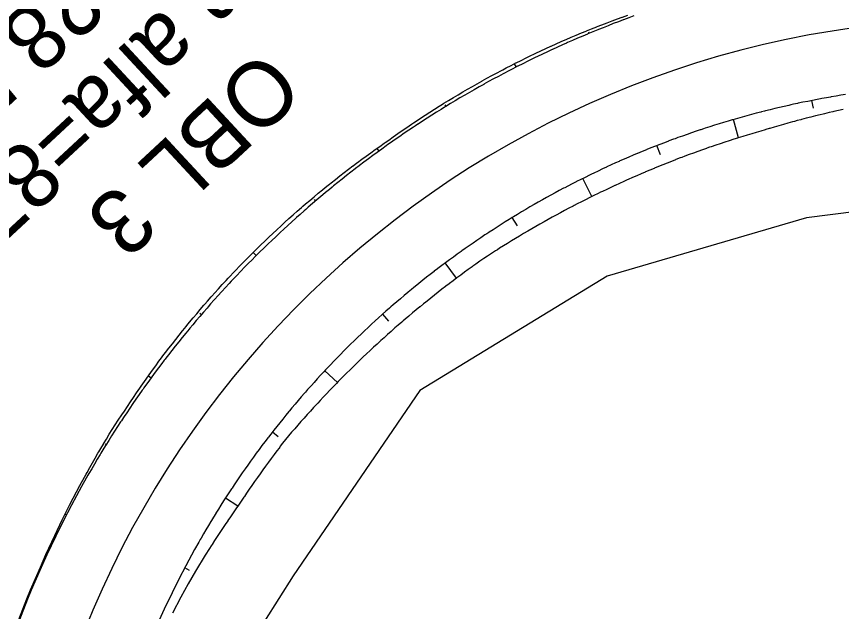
# Model space of a CAD drawing. Extents: x -583470 to -583050, y -1165714 to -1165417.
# Drawn here: x -583359.68 to -583334.17, y -1165593.45 to -1165575.06 of the extents above; entities that cross this region are included whole.
import ezdxf

# ---------------------------------------------------------------- set-up
doc = ezdxf.new("R2010")
doc.units = 0
for name, color, linetype in [('Hranice parcel', 7, 'Continuous'), ('Parcelní čísla', 7, 'Continuous'), ('Rám', 7, 'Continuous'), ('Sítě', 7, 'Continuous'), ('Šrafy', 7, 'Continuous')]:
    doc.layers.add(name, color=color, linetype=linetype)

msp = doc.modelspace()

# ---------------------------------------------------------------- linework, layer by layer
at = {"layer": 'Parcelní čísla'}
msp.add_arc((-583329.697, -1165605.137), 30, 89.2824, 176.4435, dxfattribs=at)
at = {"layer": 'Rám'}
msp.add_lwpolyline([(-583202.69, -1165538.68), (-583225.12, -1165531.51), (-583247.31, -1165545.19), (-583283.21, -1165574.06), (-583292.71, -1165580.22), (-583304.73, -1165581.14), (-583316.86, -1165578.96), (-583335.26, -1165581.29), (-583341.42, -1165583.09), (-583347.21, -1165586.62), (-583351.13, -1165592.35), (-583353.34, -1165595.85), (-583354.98, -1165601.64), (-583352.56, -1165623.43)], dxfattribs=at)
at = {"layer": 'Sítě'}
for points in [[(-583359.677, -1165593.89), (-583359.355, -1165593.062), (-583359.242, -1165592.784), (-583358.941, -1165592.078), (-583358.77, -1165591.694), (-583358.498, -1165591.106), (-583358.262, -1165590.619), (-583358.026, -1165590.148), (-583357.718, -1165589.561), (-583357.579, -1165589.304), (-583357.525, -1165589.205), (-583357.497, -1165589.155), (-583357.414, -1165589.006), (-583357.33, -1165588.857), (-583357.246, -1165588.709), (-583357.16, -1165588.562), (-583357.137, -1165588.523), (-583357.074, -1165588.415), (-583356.992, -1165588.278), (-583356.986, -1165588.268), (-583356.898, -1165588.122), (-583356.809, -1165587.977), (-583356.719, -1165587.832), (-583356.629, -1165587.687), (-583356.536, -1165587.544), (-583356.513, -1165587.51), (-583356.44, -1165587.403), (-583356.42, -1165587.374), (-583356.343, -1165587.262), (-583356.25, -1165587.119), (-583356.156, -1165586.977), (-583356.061, -1165586.835), (-583355.966, -1165586.694), (-583355.869, -1165586.553), (-583355.848, -1165586.522), (-583355.823, -1165586.486), (-583355.772, -1165586.413), (-583355.674, -1165586.273), (-583355.575, -1165586.134), (-583355.475, -1165585.996), (-583355.375, -1165585.858), (-583355.274, -1165585.72), (-583355.197, -1165585.618), (-583355.171, -1165585.584), (-583355.151, -1165585.556), (-583355.069, -1165585.447), (-583354.965, -1165585.312), (-583354.86, -1165585.177), (-583354.755, -1165585.042), (-583354.649, -1165584.908), (-583354.542, -1165584.775), (-583354.54, -1165584.773), (-583354.435, -1165584.643), (-583354.415, -1165584.618), (-583354.326, -1165584.511), (-583354.217, -1165584.379), (-583354.107, -1165584.249), (-583353.996, -1165584.119), (-583353.885, -1165583.989), (-583353.853, -1165583.952), (-583353.773, -1165583.86), (-583353.66, -1165583.732), (-583353.642, -1165583.711), (-583353.546, -1165583.605), (-583353.432, -1165583.478), (-583353.317, -1165583.351), (-583353.201, -1165583.226), (-583353.136, -1165583.156), (-583353.085, -1165583.101), (-583352.967, -1165582.977), (-583352.85, -1165582.853), (-583352.833, -1165582.836), (-583352.731, -1165582.73), (-583352.612, -1165582.608), (-583352.491, -1165582.487), (-583352.391, -1165582.386), (-583352.371, -1165582.366), (-583352.249, -1165582.246), (-583352.127, -1165582.126), (-583352.004, -1165582.007), (-583351.989, -1165581.993), (-583351.881, -1165581.889), (-583351.757, -1165581.772), (-583351.632, -1165581.655), (-583351.619, -1165581.644), (-583351.507, -1165581.539), (-583351.381, -1165581.424), (-583351.254, -1165581.31), (-583351.126, -1165581.196), (-583351.113, -1165581.184), (-583350.998, -1165581.083), (-583350.87, -1165580.971), (-583350.822, -1165580.929), (-583350.74, -1165580.859), (-583350.61, -1165580.748), (-583350.48, -1165580.638), (-583350.349, -1165580.529), (-583350.217, -1165580.42), (-583350.206, -1165580.411), (-583350.084, -1165580.312), (-583349.999, -1165580.243), (-583349.951, -1165580.205), (-583349.818, -1165580.099), (-583349.684, -1165579.993), (-583349.549, -1165579.889), (-583349.413, -1165579.784), (-583349.278, -1165579.681), (-583349.269, -1165579.675), (-583349.153, -1165579.588), (-583349.141, -1165579.579), (-583349.004, -1165579.477), (-583348.866, -1165579.376), (-583348.728, -1165579.276), (-583348.589, -1165579.177), (-583348.45, -1165579.078), (-583348.31, -1165578.98), (-583348.284, -1165578.962), (-583348.17, -1165578.882), (-583348.031, -1165578.784), (-583347.891, -1165578.685), (-583347.751, -1165578.588), (-583347.61, -1165578.492), (-583347.469, -1165578.396), (-583347.405, -1165578.353), (-583347.324, -1165578.299), (-583347.185, -1165578.207), (-583347.042, -1165578.114), (-583346.898, -1165578.021), (-583346.755, -1165577.929), (-583346.61, -1165577.838), (-583346.505, -1165577.773), (-583346.465, -1165577.748), (-583346.32, -1165577.659), (-583346.173, -1165577.571), (-583346.027, -1165577.483), (-583345.88, -1165577.396), (-583345.732, -1165577.31), (-583345.584, -1165577.225), (-583345.436, -1165577.141), (-583345.29, -1165577.059), (-583345.287, -1165577.057), (-583345.138, -1165576.975), (-583344.988, -1165576.893), (-583344.838, -1165576.812), (-583344.687, -1165576.732), (-583344.647, -1165576.711), (-583344.536, -1165576.653), (-583344.384, -1165576.574), (-583344.238, -1165576.5), (-583344.232, -1165576.497), (-583344.079, -1165576.42), (-583343.926, -1165576.344), (-583343.773, -1165576.269), (-583343.69, -1165576.229), (-583343.619, -1165576.196), (-583343.464, -1165576.123), (-583343.309, -1165576.051), (-583343.163, -1165575.985), (-583343.154, -1165575.981), (-583342.998, -1165575.911), (-583342.842, -1165575.842), (-583342.716, -1165575.786), (-583342.686, -1165575.773), (-583342.529, -1165575.706), (-583342.372, -1165575.64), (-583342.214, -1165575.574), (-583342.069, -1165575.514), (-583342.056, -1165575.509), (-583341.898, -1165575.445), (-583341.74, -1165575.382), (-583341.727, -1165575.377), (-583341.581, -1165575.32), (-583341.421, -1165575.259), (-583341.262, -1165575.199), (-583341.102, -1165575.139), (-583340.957, -1165575.086), (-583340.942, -1165575.081), (-583340.781, -1165575.023)], [(-583340.591, -1165575.048), (-583340.695, -1165575.086), (-583340.75, -1165575.106), (-583340.91, -1165575.165), (-583340.926, -1165575.171), (-583341.069, -1165575.225), (-583341.228, -1165575.286), (-583341.386, -1165575.348), (-583341.545, -1165575.41), (-583341.69, -1165575.469), (-583341.702, -1165575.474), (-583341.86, -1165575.538), (-583342.017, -1165575.603), (-583342.029, -1165575.608), (-583342.174, -1165575.669), (-583342.33, -1165575.736), (-583342.487, -1165575.803), (-583342.642, -1165575.872), (-583342.672, -1165575.885), (-583342.798, -1165575.941), (-583342.953, -1165576.011), (-583343.107, -1165576.082), (-583343.116, -1165576.086), (-583343.262, -1165576.154), (-583343.415, -1165576.226), (-583343.569, -1165576.299), (-583343.64, -1165576.334), (-583343.722, -1165576.374), (-583343.875, -1165576.449), (-583344.027, -1165576.524), (-583344.179, -1165576.601), (-583344.185, -1165576.604), (-583344.33, -1165576.678), (-583344.481, -1165576.757), (-583344.592, -1165576.814), (-583344.632, -1165576.835), (-583344.782, -1165576.915), (-583344.932, -1165576.996), (-583345.082, -1165577.077), (-583345.23, -1165577.159), (-583345.233, -1165577.161), (-583345.379, -1165577.242), (-583345.527, -1165577.326), (-583345.528, -1165577.327), (-583345.675, -1165577.411), (-583345.822, -1165577.496), (-583345.969, -1165577.582), (-583346.115, -1165577.669), (-583346.261, -1165577.757), (-583346.406, -1165577.845), (-583346.446, -1165577.87), (-583346.551, -1165577.934), (-583346.695, -1165578.024), (-583346.839, -1165578.115), (-583346.982, -1165578.206), (-583347.125, -1165578.299), (-583347.264, -1165578.39), (-583347.268, -1165578.392), (-583347.345, -1165578.443), (-583347.41, -1165578.486), (-583347.551, -1165578.58), (-583347.692, -1165578.675), (-583347.832, -1165578.771), (-583347.972, -1165578.868), (-583348.112, -1165578.966), (-583348.225, -1165579.046), (-583348.245, -1165579.06), (-583348.25, -1165579.064), (-583348.389, -1165579.163), (-583348.527, -1165579.263), (-583348.664, -1165579.363), (-583348.801, -1165579.464), (-583348.937, -1165579.566), (-583349.072, -1165579.669), (-583349.084, -1165579.678), (-583349.199, -1165579.766), (-583349.208, -1165579.772), (-583349.342, -1165579.876), (-583349.476, -1165579.981), (-583349.61, -1165580.087), (-583349.742, -1165580.193), (-583349.875, -1165580.3), (-583349.922, -1165580.338), (-583350.006, -1165580.407), (-583350.127, -1165580.507), (-583350.138, -1165580.516), (-583350.268, -1165580.625), (-583350.398, -1165580.734), (-583350.528, -1165580.845), (-583350.657, -1165580.956), (-583350.737, -1165581.026), (-583350.785, -1165581.067), (-583350.912, -1165581.18), (-583351.026, -1165581.281), (-583351.039, -1165581.293), (-583351.166, -1165581.407), (-583351.292, -1165581.521), (-583351.417, -1165581.636), (-583351.529, -1165581.74), (-583351.542, -1165581.752), (-583351.666, -1165581.869), (-583351.789, -1165581.986), (-583351.897, -1165582.089), (-583351.912, -1165582.104), (-583352.034, -1165582.222), (-583352.155, -1165582.341), (-583352.276, -1165582.461), (-583352.297, -1165582.481), (-583352.396, -1165582.581), (-583352.516, -1165582.702), (-583352.635, -1165582.824), (-583352.736, -1165582.928), (-583352.753, -1165582.946), (-583352.871, -1165583.069), (-583352.988, -1165583.192), (-583353.039, -1165583.247), (-583353.104, -1165583.316), (-583353.22, -1165583.441), (-583353.335, -1165583.566), (-583353.449, -1165583.692), (-583353.544, -1165583.798), (-583353.563, -1165583.819), (-583353.676, -1165583.946), (-583353.756, -1165584.037), (-583353.788, -1165584.074), (-583353.9, -1165584.202), (-583354.011, -1165584.331), (-583354.121, -1165584.461), (-583354.23, -1165584.591), (-583354.319, -1165584.698), (-583354.339, -1165584.722), (-583354.445, -1165584.85), (-583354.447, -1165584.853), (-583354.555, -1165584.985), (-583354.662, -1165585.117), (-583354.768, -1165585.25), (-583354.873, -1165585.384), (-583354.978, -1165585.518), (-583355.061, -1165585.625), (-583355.082, -1165585.652), (-583355.108, -1165585.686), (-583355.185, -1165585.788), (-583355.287, -1165585.923), (-583355.389, -1165586.06), (-583355.49, -1165586.197), (-583355.591, -1165586.334), (-583355.69, -1165586.472), (-583355.742, -1165586.544), (-583355.767, -1165586.579), (-583355.789, -1165586.61), (-583355.887, -1165586.749), (-583355.984, -1165586.889), (-583356.081, -1165587.029), (-583356.177, -1165587.169), (-583356.272, -1165587.31), (-583356.347, -1165587.422), (-583356.367, -1165587.452), (-583356.437, -1165587.559), (-583356.46, -1165587.594), (-583356.553, -1165587.736), (-583356.645, -1165587.879), (-583356.737, -1165588.023), (-583356.827, -1165588.167), (-583356.917, -1165588.311), (-583356.923, -1165588.32), (-583357.006, -1165588.456), (-583357.071, -1165588.563), (-583357.094, -1165588.601), (-583357.182, -1165588.747), (-583357.269, -1165588.894), (-583357.354, -1165589.04), (-583357.44, -1165589.188), (-583357.468, -1165589.237), (-583357.524, -1165589.335), (-583357.667, -1165589.59), (-583357.982, -1165590.171), (-583358.224, -1165590.638), (-583358.465, -1165591.122), (-583358.743, -1165591.706), (-583358.917, -1165592.089), (-583359.221, -1165592.793), (-583359.335, -1165593.07), (-583359.658, -1165593.897)], [(-583334.047, -1165577.477), (-583334.194, -1165577.5), (-583334.341, -1165577.524), (-583334.488, -1165577.549), (-583334.517, -1165577.555), (-583334.635, -1165577.575), (-583334.781, -1165577.602), (-583334.825, -1165577.61), (-583334.927, -1165577.629), (-583335.073, -1165577.658), (-583335.219, -1165577.687), (-583335.365, -1165577.716), (-583335.511, -1165577.747), (-583335.537, -1165577.752), (-583335.656, -1165577.778), (-583335.739, -1165577.796), (-583335.802, -1165577.81), (-583335.947, -1165577.843), (-583336.092, -1165577.877), (-583336.237, -1165577.911), (-583336.381, -1165577.946), (-583336.526, -1165577.982), (-583336.549, -1165577.988), (-583336.647, -1165578.013), (-583336.67, -1165578.019), (-583336.814, -1165578.056), (-583336.958, -1165578.094), (-583337.102, -1165578.133), (-583337.245, -1165578.173), (-583337.388, -1165578.214), (-583337.531, -1165578.255), (-583337.547, -1165578.259), (-583337.551, -1165578.261), (-583337.674, -1165578.297), (-583337.817, -1165578.34), (-583337.959, -1165578.383), (-583338.101, -1165578.427), (-583338.243, -1165578.473), (-583338.385, -1165578.518), (-583338.438, -1165578.536), (-583338.526, -1165578.565), (-583338.543, -1165578.57), (-583338.667, -1165578.612), (-583338.808, -1165578.66), (-583338.949, -1165578.709), (-583339.089, -1165578.759), (-583339.229, -1165578.809), (-583339.32, -1165578.842), (-583339.369, -1165578.86), (-583339.508, -1165578.912), (-583339.522, -1165578.917), (-583339.648, -1165578.964), (-583339.787, -1165579.018), (-583339.925, -1165579.072), (-583340.064, -1165579.126), (-583340.191, -1165579.177), (-583340.202, -1165579.182), (-583340.34, -1165579.238), (-583340.477, -1165579.295), (-583340.488, -1165579.299), (-583340.614, -1165579.353), (-583340.751, -1165579.411), (-583340.888, -1165579.47), (-583341.024, -1165579.53), (-583341.05, -1165579.541), (-583341.16, -1165579.59), (-583341.296, -1165579.652), (-583341.431, -1165579.714), (-583341.439, -1165579.717), (-583341.566, -1165579.777), (-583341.701, -1165579.84), (-583341.835, -1165579.904), (-583341.897, -1165579.934), (-583341.969, -1165579.969), (-583342.103, -1165580.035), (-583342.236, -1165580.101), (-583342.369, -1165580.168), (-583342.374, -1165580.17), (-583342.501, -1165580.236), (-583342.633, -1165580.304), (-583342.73, -1165580.355), (-583342.765, -1165580.373), (-583342.897, -1165580.443), (-583343.028, -1165580.513), (-583343.159, -1165580.585), (-583343.289, -1165580.657), (-583343.291, -1165580.658), (-583343.419, -1165580.729), (-583343.548, -1165580.802), (-583343.549, -1165580.803), (-583343.677, -1165580.876), (-583343.806, -1165580.951), (-583343.935, -1165581.026), (-583344.063, -1165581.102), (-583344.19, -1165581.179), (-583344.317, -1165581.257), (-583344.352, -1165581.278), (-583344.444, -1165581.335), (-583344.57, -1165581.413), (-583344.696, -1165581.493), (-583344.822, -1165581.573), (-583344.947, -1165581.653), (-583345.069, -1165581.733), (-583345.071, -1165581.735), (-583345.139, -1165581.78), (-583345.196, -1165581.817), (-583345.319, -1165581.9), (-583345.443, -1165581.983), (-583345.565, -1165582.067), (-583345.688, -1165582.152), (-583345.81, -1165582.237), (-583345.909, -1165582.307), (-583345.926, -1165582.319), (-583345.931, -1165582.323), (-583346.052, -1165582.41), (-583346.173, -1165582.497), (-583346.293, -1165582.585), (-583346.413, -1165582.673), (-583346.532, -1165582.763), (-583346.651, -1165582.852), (-583346.661, -1165582.86), (-583346.761, -1165582.937), (-583346.769, -1165582.943), (-583346.887, -1165583.034), (-583347.004, -1165583.125), (-583347.121, -1165583.218), (-583347.237, -1165583.311), (-583347.353, -1165583.404), (-583347.394, -1165583.438), (-583347.468, -1165583.498), (-583347.573, -1165583.585), (-583347.583, -1165583.593), (-583347.697, -1165583.689), (-583347.811, -1165583.785), (-583347.924, -1165583.881), (-583348.037, -1165583.978), (-583348.107, -1165584.04), (-583348.149, -1165584.076), (-583348.261, -1165584.175), (-583348.36, -1165584.263), (-583348.372, -1165584.273), (-583348.482, -1165584.373), (-583348.592, -1165584.473), (-583348.702, -1165584.574), (-583348.8, -1165584.665), (-583348.811, -1165584.675), (-583348.92, -1165584.777), (-583349.028, -1165584.88), (-583349.122, -1165584.97), (-583349.135, -1165584.983), (-583349.242, -1165585.086), (-583349.348, -1165585.19), (-583349.454, -1165585.295), (-583349.472, -1165585.313), (-583349.559, -1165585.4), (-583349.664, -1165585.506), (-583349.768, -1165585.613), (-583349.856, -1165585.704), (-583349.871, -1165585.72), (-583349.974, -1165585.827), (-583350.077, -1165585.935), (-583350.121, -1165585.983), (-583350.178, -1165586.044), (-583350.279, -1165586.153), (-583350.38, -1165586.263), (-583350.48, -1165586.373), (-583350.563, -1165586.466), (-583350.58, -1165586.484), (-583350.678, -1165586.595), (-583350.748, -1165586.674), (-583350.777, -1165586.707), (-583350.874, -1165586.819), (-583350.971, -1165586.932), (-583351.068, -1165587.045), (-583351.164, -1165587.159), (-583351.242, -1165587.252), (-583351.259, -1165587.273), (-583351.352, -1165587.386), (-583351.354, -1165587.388), (-583351.448, -1165587.504), (-583351.541, -1165587.62), (-583351.634, -1165587.736), (-583351.726, -1165587.853), (-583351.818, -1165587.97), (-583351.89, -1165588.064), (-583351.909, -1165588.088), (-583351.932, -1165588.118), (-583351.999, -1165588.206), (-583352.089, -1165588.325), (-583352.178, -1165588.444), (-583352.266, -1165588.564), (-583352.354, -1165588.684), (-583352.441, -1165588.805), (-583352.486, -1165588.868), (-583352.508, -1165588.899), (-583352.528, -1165588.926), (-583352.613, -1165589.048), (-583352.699, -1165589.17), (-583352.783, -1165589.292), (-583352.867, -1165589.415), (-583352.95, -1165589.538), (-583353.016, -1165589.637), (-583353.033, -1165589.662), (-583353.095, -1165589.756), (-583353.115, -1165589.787), (-583353.196, -1165589.911), (-583353.277, -1165590.036), (-583353.357, -1165590.162), (-583353.436, -1165590.288), (-583353.514, -1165590.414), (-583353.519, -1165590.422), (-583353.592, -1165590.541), (-583353.649, -1165590.635), (-583353.67, -1165590.668), (-583353.746, -1165590.796), (-583353.822, -1165590.924), (-583353.897, -1165591.052), (-583353.972, -1165591.181), (-583353.997, -1165591.225), (-583354.046, -1165591.311), (-583354.171, -1165591.533), (-583354.447, -1165592.042), (-583354.659, -1165592.45), (-583354.869, -1165592.874), (-583355.112, -1165593.385), (-583355.264, -1165593.72)], [(-583334.123, -1165577.939), (-583334.266, -1165577.971), (-583334.409, -1165578.003), (-583334.438, -1165578.009), (-583334.552, -1165578.036), (-583334.695, -1165578.069), (-583334.737, -1165578.079), (-583334.837, -1165578.103), (-583334.979, -1165578.138), (-583335.121, -1165578.173), (-583335.263, -1165578.209), (-583335.405, -1165578.246), (-583335.43, -1165578.253), (-583335.546, -1165578.283), (-583335.627, -1165578.305), (-583335.688, -1165578.321), (-583335.829, -1165578.36), (-583335.969, -1165578.399), (-583336.11, -1165578.439), (-583336.25, -1165578.48), (-583336.39, -1165578.521), (-583336.413, -1165578.528), (-583336.508, -1165578.556), (-583336.53, -1165578.563), (-583336.67, -1165578.605), (-583336.809, -1165578.648), (-583336.949, -1165578.689), (-583337.089, -1165578.731), (-583337.228, -1165578.773), (-583337.368, -1165578.817), (-583337.387, -1165578.823), (-583337.507, -1165578.86), (-583337.645, -1165578.905), (-583337.784, -1165578.95), (-583337.922, -1165578.996), (-583338.06, -1165579.042), (-583338.198, -1165579.089), (-583338.251, -1165579.107), (-583338.336, -1165579.137), (-583338.352, -1165579.142), (-583338.473, -1165579.185), (-583338.611, -1165579.234), (-583338.747, -1165579.284), (-583338.884, -1165579.334), (-583339.021, -1165579.385), (-583339.109, -1165579.418), (-583339.157, -1165579.436), (-583339.293, -1165579.488), (-583339.306, -1165579.493), (-583339.428, -1165579.541), (-583339.564, -1165579.594), (-583339.699, -1165579.648), (-583339.834, -1165579.703), (-583339.958, -1165579.754), (-583339.969, -1165579.758), (-583340.103, -1165579.814), (-583340.237, -1165579.87), (-583340.248, -1165579.875), (-583340.371, -1165579.927), (-583340.505, -1165579.985), (-583340.638, -1165580.044), (-583340.771, -1165580.103), (-583340.796, -1165580.114), (-583340.904, -1165580.162), (-583341.036, -1165580.222), (-583341.168, -1165580.283), (-583341.176, -1165580.287), (-583341.3, -1165580.345), (-583341.432, -1165580.407), (-583341.563, -1165580.469), (-583341.624, -1165580.498), (-583341.694, -1165580.533), (-583341.825, -1165580.596), (-583341.955, -1165580.661), (-583342.085, -1165580.726), (-583342.09, -1165580.728), (-583342.215, -1165580.792), (-583342.345, -1165580.858), (-583342.44, -1165580.907), (-583342.474, -1165580.925), (-583342.603, -1165580.992), (-583342.732, -1165581.061), (-583342.86, -1165581.129), (-583342.99, -1165581.2), (-583343.116, -1165581.269), (-583343.243, -1165581.339), (-583343.37, -1165581.41), (-583343.497, -1165581.482), (-583343.623, -1165581.554), (-583343.749, -1165581.627), (-583343.875, -1165581.7), (-583344, -1165581.775), (-583344.035, -1165581.795), (-583344.125, -1165581.849), (-583344.25, -1165581.924), (-583344.374, -1165582), (-583344.498, -1165582.077), (-583344.622, -1165582.154), (-583344.743, -1165582.229), (-583344.812, -1165582.274), (-583344.868, -1165582.309), (-583344.991, -1165582.388), (-583345.113, -1165582.467), (-583345.235, -1165582.547), (-583345.355, -1165582.63), (-583345.474, -1165582.715), (-583345.571, -1165582.784), (-583345.592, -1165582.799), (-583345.711, -1165582.884), (-583345.829, -1165582.97), (-583345.946, -1165583.056), (-583346.063, -1165583.143), (-583346.18, -1165583.231), (-583346.296, -1165583.319), (-583346.306, -1165583.326), (-583346.404, -1165583.402), (-583346.412, -1165583.407), (-583346.527, -1165583.496), (-583346.642, -1165583.586), (-583346.757, -1165583.676), (-583346.871, -1165583.766), (-583346.984, -1165583.857), (-583347.025, -1165583.89), (-583347.098, -1165583.949), (-583347.201, -1165584.034), (-583347.211, -1165584.041), (-583347.323, -1165584.134), (-583347.435, -1165584.227), (-583347.547, -1165584.321), (-583347.658, -1165584.415), (-583347.728, -1165584.474), (-583347.769, -1165584.51), (-583347.879, -1165584.605), (-583347.978, -1165584.691), (-583347.989, -1165584.701), (-583348.099, -1165584.797), (-583348.208, -1165584.894), (-583348.316, -1165584.991), (-583348.414, -1165585.079), (-583348.424, -1165585.089), (-583348.532, -1165585.187), (-583348.639, -1165585.286), (-583348.733, -1165585.373), (-583348.746, -1165585.386), (-583348.853, -1165585.485), (-583348.959, -1165585.586), (-583349.064, -1165585.687), (-583349.082, -1165585.704), (-583349.169, -1165585.788), (-583349.274, -1165585.89), (-583349.378, -1165585.992), (-583349.467, -1165586.08), (-583349.482, -1165586.095), (-583349.585, -1165586.198), (-583349.688, -1165586.302), (-583349.733, -1165586.348), (-583349.79, -1165586.406), (-583349.892, -1165586.511), (-583349.993, -1165586.616), (-583350.094, -1165586.722), (-583350.178, -1165586.81), (-583350.194, -1165586.828), (-583350.294, -1165586.934), (-583350.365, -1165587.01), (-583350.394, -1165587.041), (-583350.493, -1165587.149), (-583350.591, -1165587.257), (-583350.689, -1165587.366), (-583350.787, -1165587.475), (-583350.866, -1165587.564), (-583350.884, -1165587.584), (-583350.981, -1165587.694), (-583351.077, -1165587.804), (-583351.173, -1165587.915), (-583351.268, -1165588.026), (-583351.362, -1165588.139), (-583351.451, -1165588.255), (-583351.522, -1165588.347), (-583351.54, -1165588.371), (-583351.562, -1165588.4), (-583351.628, -1165588.488), (-583351.716, -1165588.605), (-583351.803, -1165588.722), (-583351.89, -1165588.84), (-583351.976, -1165588.958), (-583352.062, -1165589.077), (-583352.107, -1165589.139), (-583352.128, -1165589.17), (-583352.147, -1165589.196), (-583352.232, -1165589.316), (-583352.316, -1165589.435), (-583352.399, -1165589.556), (-583352.482, -1165589.676), (-583352.564, -1165589.797), (-583352.629, -1165589.894), (-583352.646, -1165589.919), (-583352.708, -1165590.011), (-583352.728, -1165590.04), (-583352.81, -1165590.161), (-583352.895, -1165590.281), (-583352.979, -1165590.401), (-583353.062, -1165590.522), (-583353.145, -1165590.643), (-583353.15, -1165590.65), (-583353.228, -1165590.764), (-583353.288, -1165590.854), (-583353.309, -1165590.886), (-583353.391, -1165591.008), (-583353.472, -1165591.131), (-583353.552, -1165591.254), (-583353.632, -1165591.377), (-583353.658, -1165591.418), (-583353.711, -1165591.501), (-583353.845, -1165591.714), (-583354.141, -1165592.204), (-583354.368, -1165592.598), (-583354.594, -1165593.008), (-583354.854, -1165593.505)]]:
    msp.add_lwpolyline(points, dxfattribs=at)
at = {"layer": 'Šrafy'}
for p, q in [((-583341.994, -1165575.539), (-583341.975, -1165575.586)), ((-583344.289, -1165576.526), (-583344.236, -1165576.63)), ((-583335.041, -1165577.902), (-583335.088, -1165577.662)), ((-583346.438, -1165577.798), (-583346.408, -1165577.847)), ((-583337.353, -1165578.812), (-583337.516, -1165578.252)), ((-583348.543, -1165579.144), (-583348.481, -1165579.23)), ((-583339.77, -1165579.344), (-583339.882, -1165579.056)), ((-583341.889, -1165580.628), (-583342.167, -1165580.068)), ((-583350.48, -1165580.721), (-583350.439, -1165580.769)), ((-583344.194, -1165581.538), (-583344.353, -1165581.28)), ((-583352.364, -1165582.359), (-583352.27, -1165582.454)), ((-583346.073, -1165583.151), (-583346.422, -1165582.682)), ((-583354.012, -1165584.236), (-583353.964, -1165584.277)), ((-583348.167, -1165584.476), (-583348.357, -1165584.263)), ((-583355.598, -1165586.166), (-583355.512, -1165586.227)), ((-583349.757, -1165586.372), (-583350.144, -1165586.01)), ((-583351.586, -1165588.051), (-583351.768, -1165587.909)), ((-583356.941, -1165588.272), (-583356.906, -1165588.293)), ((-583352.833, -1165590.194), (-583353.217, -1165589.946)), ((-583358.174, -1165590.444), (-583358.134, -1165590.464)), ((-583354.327, -1165592.183), (-583354.478, -1165592.103)), ((-583359.203, -1165592.722), (-583359.192, -1165592.726))]:
    msp.add_line(p, q, dxfattribs=at)

# ---------------------------------------------------------------- texts
at = {"layer": 'Hranice parcel'}
for s, p in [('R=30m alfa=87.16%%d', (-583348.209, -1165568.33)), ('   z=11.41', (-583356.719, -1165568.042)), ('  T=28.55', (-583354.704, -1165570.266)), ('OBL 3', (-583352.078, -1165576.014))]:
    msp.add_text(s, height=2, rotation=222.8629, dxfattribs=at).set_placement(p)

doc.saveas('drawing.dxf')
